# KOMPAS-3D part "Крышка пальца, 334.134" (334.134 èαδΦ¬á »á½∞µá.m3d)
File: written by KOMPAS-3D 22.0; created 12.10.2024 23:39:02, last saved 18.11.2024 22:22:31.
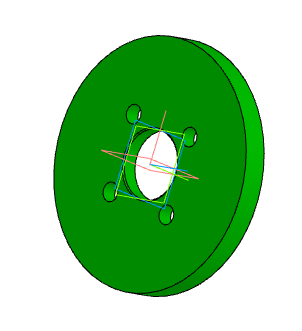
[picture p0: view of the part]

Document properties: Автор: aleksander.larionov.10@gmail.com; Полное имя файла: C:\Мои папки\Работа\Крышки, фланцы\334.134\334.134 Крышка пальца.m3d

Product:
- Part/product: Крышка пальца  | designation 334.134
    Материал: Сталь 45 ГОСТ 1050-2013 (density 7810 kg/m3)
    Масса: 2.920453

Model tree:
1. Эскиз:1
2. Элемент вращения:1
     Угол 1 = 360
3. Эскиз:2  (with: Элемент вращения:1)
4. Отверстие:1
     Глубина выреза = 12; Диаметр отверстия = 50; Угол конуса дна = 118
5. Отверстие:2  (with: Элемент вращения:1)
     Глубина выреза = 40; Диаметр отверстия = 14; Угол конуса дна = 118; Расстояние 1 = -28.2843; Расстояние 2 = 28.2843
6. Отверстие:3  (with: Элемент вращения:1)
     Глубина выреза = 40; Диаметр отверстия = 14; Угол конуса дна = 118; Расстояние 1 = 28.2843; Расстояние 2 = 28.2843
7. Отверстие:4  (with: Элемент вращения:1)
     Глубина выреза = 40; Диаметр отверстия = 14; Угол конуса дна = 118; Расстояние 1 = -28.2843; Расстояние 2 = -28.2843
8. Отверстие:5  (with: Элемент вращения:1)
     Глубина выреза = 40; Диаметр отверстия = 14; Угол конуса дна = 118; Расстояние 1 = 28.2843; Расстояние 2 = -28.2843
9. Фаска:1  (with: Отверстие:1)  (labels: Сталь 45 ГОСТ 1050-2013)
     Угол = 45; Длина 1 = 1; Длина 2 = 1

Expressions: 180/2; 109/2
